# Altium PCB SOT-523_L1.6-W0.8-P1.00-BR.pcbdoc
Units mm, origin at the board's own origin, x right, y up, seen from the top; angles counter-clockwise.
Board outline 14.73 x 14.45 mm, 2 copper layers (Top Layer, Bottom Layer), stack 0 mm thick; 1 components, 0 nets, 3 pads, 0 vias.
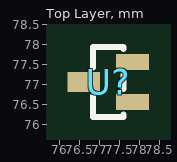
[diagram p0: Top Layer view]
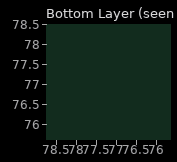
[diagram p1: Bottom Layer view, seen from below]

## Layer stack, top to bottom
Top Layer: signal copper (thickness not stored)
Bottom Layer: signal copper (thickness not stored)

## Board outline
84.582,69.85 69.85,69.85 69.85,84.303 84.582,84.303

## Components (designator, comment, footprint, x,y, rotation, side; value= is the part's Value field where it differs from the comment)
U? "" SOT-523_L1.6-W0.8-P1.00-BR 77.216,77.076 r0 top

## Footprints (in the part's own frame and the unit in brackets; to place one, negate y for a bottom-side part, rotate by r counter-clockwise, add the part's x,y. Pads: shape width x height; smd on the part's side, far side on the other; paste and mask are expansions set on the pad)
SOT-523_L1.6-W0.8-P1.00-BR [mm]
  rect 0.816x0.4 smd: 1(0.608,-0.5) 2(0.608,0.5)
  rect 0.816x0.5 smd: 3(-0.608,0)
  silkscreen extent -0.38,-0.88 0.38,0.88

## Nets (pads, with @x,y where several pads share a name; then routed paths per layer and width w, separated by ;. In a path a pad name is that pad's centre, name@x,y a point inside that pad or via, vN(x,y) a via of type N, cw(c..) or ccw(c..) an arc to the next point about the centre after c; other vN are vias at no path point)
pads on no net: U?.1 U?.2 U?.3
